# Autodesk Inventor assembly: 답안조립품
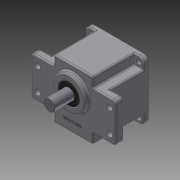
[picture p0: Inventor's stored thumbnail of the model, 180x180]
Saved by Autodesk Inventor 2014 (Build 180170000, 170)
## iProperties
Created: 2015-07
Part Number: 답안조립품
Document SubType Name: Assembly
Designer: Administrator
Author: Administrator
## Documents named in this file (12)
- C:\Users\Administrator\Desktop\450727V1008\답안조립품.iam
- C:\Users\Administrator\Desktop\450727V1008\본체.ipt
- C:\Users\Administrator\Desktop\450727V1008\커버.ipt
- C:\Users\Administrator\Desktop\450727V1008\오일실 17x32x8.ipt
- C:\Users\Administrator\Desktop\450727V1008\오일실 8x22x7.ipt
- C:\Users\Administrator\Desktop\450727V1008\베어링 6003.ipt
- 베어링 6003.ipt
- C:\Users\Administrator\Desktop\450727V1008\베어링 608.ipt
- 베어링 608.ipt
- C:\Users\Administrator\Desktop\450727V1008\메인축.ipt
- C:\Users\Administrator\Desktop\450727V1008\서브축.ipt
- C:\Users\Administrator\Desktop\450727V1008\M4x0.5x16.ipt
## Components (4 placed, 1 different names)
1. M4x0.5x12:1
2. M4x0.5x12:2
3. M4x0.5x12:3
4. M4x0.5x12:4
